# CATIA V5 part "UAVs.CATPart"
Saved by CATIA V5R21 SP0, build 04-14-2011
Part number: Part1
Bounding box of the stored display mesh (mm): x -4879 to 2108.579, y -5454 to 5454, z -500 to 500
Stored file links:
  G:\CATIA\UAVs.CATPart
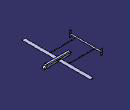
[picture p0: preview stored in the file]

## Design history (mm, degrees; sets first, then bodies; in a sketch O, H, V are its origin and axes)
Body1 (main body)
  Sketch1 on yz-plane, origin (0, 0, 0), H (0, 1, 0), V (0, 0, 1)
    line L1 (254, 254) -> (254, -254)
    line L2 (254, -254) -> (-254, -254)
    line L3 (-254, -254) -> (-254, 254)
    line L4 (-254, 254) -> (254, 254)
    length L1 = 508
    length L4 = 508
    vertical: L1 V, L3 V
    horizontal: L2 H, L4 H
    equidistance: L1 L3 O, L2 L4 O
  Pad1: profile Sketch1, direction (1, 0, 0), length 2250, mirrored extent
  Chamfer1: length 508, angle 45, on edge [face of Pad1 from Sketch1.L4 | end face of Pad1]
  Fillet1: radius 300, on edge [face of Pad1 from Sketch1.L4 | face of Chamfer1]
  Fillet2: radius 100, on edge [face of Chamfer1 | face of Pad1 from Sketch1.L2]
  Chamfer2: length 508, angle 20, on edge [start face of Pad1 | face of Pad1 from Sketch1.L2]
  Fillet3: radius 100, on edge [face of Pad1 from Sketch1.L4 | face of Chamfer2]
  Fillet4: radius 250, on edge [face of Chamfer2 | face of Pad1 from Sketch1.L2]
  Fillet5: radius 100, on edge [face of Pad1 from Sketch1.L4 | face of Pad1 from Sketch1.L1]; edge [face of Pad1 from Sketch1.L3 | face of Pad1 from Sketch1.L4]
  Plane1: type Offset, RefPlane zx-plane, Offset 254
  Sketch2 on Plane1, origin (0, 254, 0), H (-1, 0, 0), V (0, 0, 1)
    spline S1 through (0, 0) (348.6352, 49.5465) (540, 0) (348.6352, -49.5465) (0, 0)
    point P1 (0, 0)
    point P2 (540, 0)
    point P3 (0, 0)
    point P4 (348.6352, 49.5465)
    point P5 (348.6352, -49.5465)
    distance P2 P3 = 540
    distance P4 P5 = 99.0929
    coincidence: P1 O, P2 H, P3 O
    symmetry: P4 P5 H
  Pad2: profile Sketch2, direction (0, 1, 0), length 5200
  Mirror1: of Pad2, about zx-plane
  Plane2: type Offset, RefPlane yz-plane, Offset 254, reversed
  Sketch3 on Plane2, origin (-254, 0, 0), H (0, 1, 0), V (0, 0, 1)
    circle A1 centre (1500, 0) radius 40
    point P1 (1500, 0)
    reference intersected line E1 through (0, 0) direction (0, 1) from zx-plane
    circle A2 centre (-1500, 0) radius 40
    radius A1 = 40
    distance P1 V = 1500
    coincidence: P1 H
    symmetry: A1 A2 E1
  Pad3: profile Sketch3, direction (-1, 0, 0), length 4500
  Plane3: type Offset, RefPlane Plane2, Offset 4500, reversed
  Sketch4 on zx-plane, origin (0, 0, 0), H (-1, 0, 0), V (0, 0, 1)
    construction line L1 (0, 0) -> (4754, 0)
    point P1 (4754, 0)
    reference intersected line E1 through (4754, 0) direction (0, -1) from Plane3
    axis line L2 (4754, 0) -> (4879, 0)
    point P2 (4879, 0)
    spline S1 through (4629, 0) (4802.5166, 37.1621) (4879, 0) (4802.5166, -37.1621) (4629, 0)
    point P3 (4629, 0)
    point P4 (4879, 0)
    point P5 (4629, 0)
    point P6 (4802.5166, 37.1621)
    point P7 (4802.5166, -37.1621)
    length L2 = 125
    distance P4 P5 = 250
    horizontal: L1 H, L2 H
    coincidence: P1 E1, P3 L1, P4 P2, P5 P3
    symmetry: P6 P7 L2
  Pad4: profile Sketch4, direction (0, 1, 0), length 2500, mirrored extent
  Sketch5 on xy-plane, origin (0, 0, 0), H (1, 0, 0), V (0, 1, 0)
    point P1 (-4879, -2500)
    point P2 (-4629, -2500)
    spline S1 through (-4629, -2500) (-4792.3403, -2475.0215) (-4879, -2500) (-4792.3403, -2524.9785) (-4629, -2500)
    spline S2 through (-4629, 2500) (-4792.3403, 2475.0215) (-4879, 2500) (-4792.3403, 2524.9785) (-4629, 2500)
    point P3 (-4629, -2500)
    point P4 (-4879, -2500)
    point P5 (-4629, -2500)
    point P6 (-4792.3403, -2524.9785)
    point P7 (-4792.3403, -2475.0215)
    point P8 (-4629, 2500)
    point P9 (-4629, 2500)
    distance P5 P4 = 250
    distance P7 P6 = 49.957
    coincidence: P3 P2, P4 P1, P5 P2, P9 P8
  Pad5: profile Sketch5, direction (0, 0, 1), length 500, mirrored extent
  Fillet6: radius 50, on edge [face of Mirror1 | face of Pad1 from Sketch1.L3]; edge [face of Pad1 from Sketch1.L1 | face of Pad2 from Sketch2.S1]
